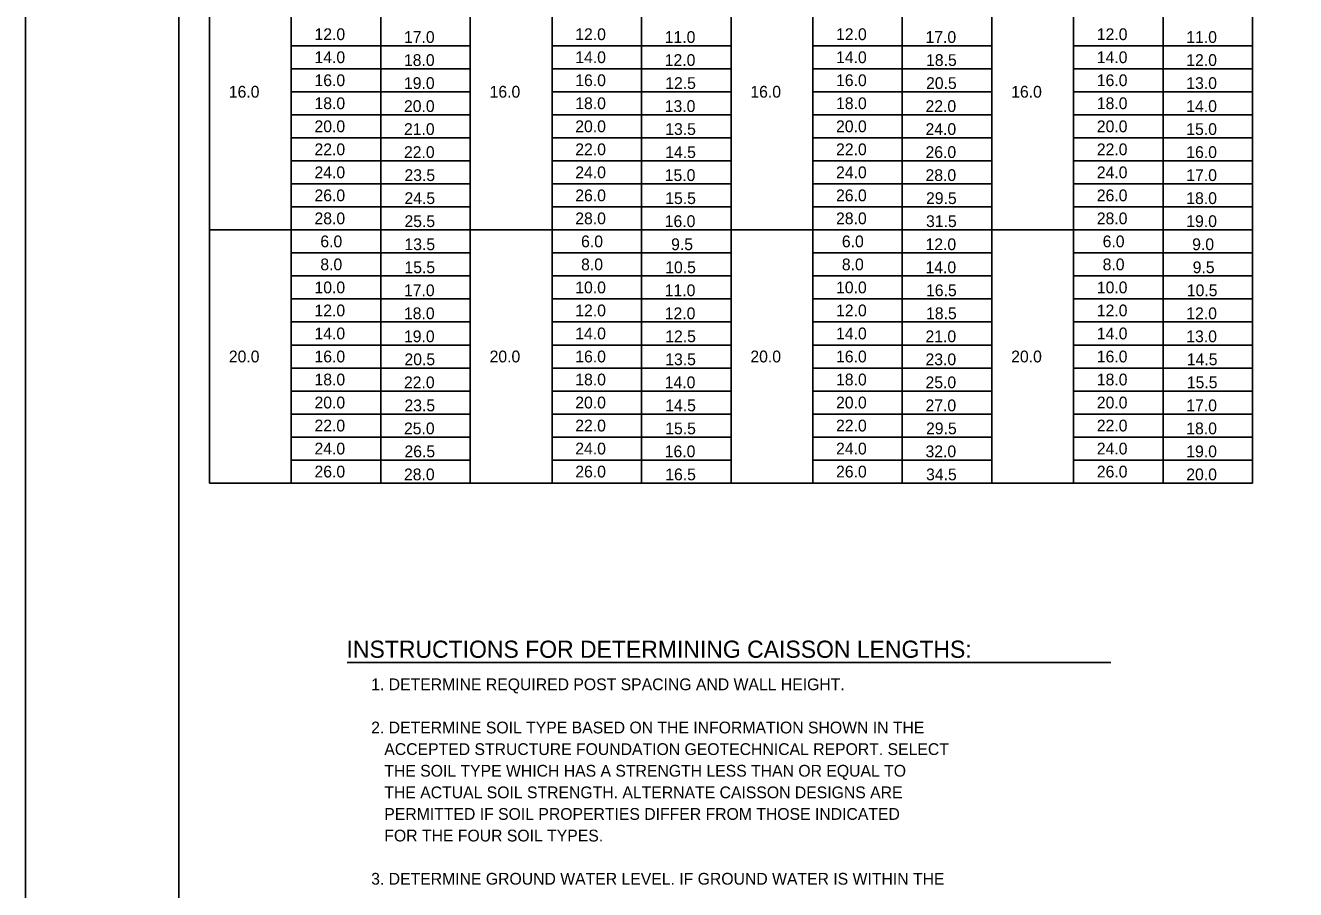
# Model space of a CAD drawing. Extents: x 3475 to 6558, y -3780 to 1166.
# Drawn here: x 3761.3 to 4092.6, y -3449.2 to -3224 of the extents above; entities that cross this region are included whole.
import ezdxf

# ---------------------------------------------------------------- set-up
doc = ezdxf.new("R2010")
doc.units = 0
for name, color, linetype in [('1', 7, 'Continuous'), ('2', 7, 'Continuous'), ('PLT-BNDY', 7, 'Continuous')]:
    doc.layers.add(name, color=color, linetype=linetype)

msp = doc.modelspace()

# ---------------------------------------------------------------- linework, layer by layer
at = {"layer": '1'}
for p, q in [((3809.33, -3015.3), (3809.33, -3343.24)), ((4081.34, -3015.3), (4081.34, -3343.24)), ((3877.34, -3055.3), (3877.34, -3343.24)), ((3945.34, -3055.3), (3945.34, -3343.24)), ((4013.34, -3055.3), (4013.34, -3343.24)), ((3830.67, -3343.24), (3830.67, -3110.49)), ((3854, -3110.49), (3854, -3343.24)), ((3898.67, -3343.24), (3898.67, -3110.49)), ((3922, -3110.49), (3922, -3343.24)), ((3966.67, -3343.24), (3966.67, -3110.49)), ((3990, -3110.49), (3990, -3343.24)), ((4034.67, -3343.24), (4034.67, -3110.49)), ((4058, -3110.49), (4058, -3343.24)), ((3830.67, -3229.24), (3877.34, -3229.24)), ((3898.67, -3229.24), (3945.34, -3229.24)), ((3966.67, -3229.24), (4013.34, -3229.24)), ((4034.67, -3229.24), (4081.34, -3229.24)), ((3830.67, -3235.24), (3877.34, -3235.24)), ((3898.67, -3235.24), (3945.34, -3235.24)), ((3966.67, -3235.24), (4013.34, -3235.24)), ((4034.67, -3235.24), (4081.34, -3235.24)), ((3830.67, -3241.24), (3877.34, -3241.24)), ((3898.67, -3241.24), (3945.34, -3241.24)), ((3966.67, -3241.24), (4013.34, -3241.24)), ((4034.67, -3241.24), (4081.34, -3241.24)), ((3830.67, -3247.24), (3877.34, -3247.24)), ((3898.67, -3247.24), (3945.34, -3247.24)), ((3966.67, -3247.24), (4013.34, -3247.24)), ((4034.67, -3247.24), (4081.34, -3247.24)), ((3830.67, -3253.24), (3877.34, -3253.24)), ((3898.67, -3253.24), (3945.34, -3253.24)), ((3966.67, -3253.24), (4013.34, -3253.24)), ((4034.67, -3253.24), (4081.34, -3253.24)), ((3830.67, -3259.24), (3877.34, -3259.24)), ((3898.67, -3259.24), (3945.34, -3259.24)), ((3966.67, -3259.24), (4013.34, -3259.24)), ((4034.67, -3259.24), (4081.34, -3259.24)), ((3830.67, -3265.24), (3877.34, -3265.24)), ((3898.67, -3265.24), (3945.34, -3265.24)), ((3966.67, -3265.24), (4013.34, -3265.24)), ((4034.67, -3265.24), (4081.34, -3265.24)), ((3830.67, -3271.24), (3877.34, -3271.24)), ((3898.67, -3271.24), (3945.34, -3271.24)), ((3966.67, -3271.24), (4013.34, -3271.24)), ((4034.67, -3271.24), (4081.34, -3271.24)), ((3809.33, -3277.25), (4081.34, -3277.25)), ((3865.67, -3281), (3865.67, -3281)), ((3933.67, -3281), (3933.67, -3281)), ((4001.67, -3281), (4001.67, -3281)), ((4069.67, -3281), (4069.67, -3281)), ((3830.67, -3283.25), (3877.34, -3283.25)), ((3830.67, -3283.25), (3877.34, -3283.25)), ((3898.67, -3283.25), (3945.34, -3283.25)), ((3966.67, -3283.25), (4013.34, -3283.25)), ((4034.67, -3283.25), (4081.34, -3283.25)), ((3830.67, -3289.25), (3877.34, -3289.25)), ((3898.67, -3289.25), (3945.34, -3289.25)), ((3966.67, -3289.25), (4013.34, -3289.25)), ((4034.67, -3289.25), (4081.34, -3289.25)), ((3830.67, -3295.25), (3877.34, -3295.25)), ((3898.67, -3295.25), (3945.34, -3295.25)), ((3966.67, -3295.25), (4013.34, -3295.25)), ((4034.67, -3295.25), (4081.34, -3295.25)), ((3830.67, -3301.25), (3877.34, -3301.25)), ((3898.67, -3301.25), (3945.34, -3301.25)), ((3966.67, -3301.25), (4013.34, -3301.25)), ((4034.67, -3301.25), (4081.34, -3301.25)), ((3830.67, -3307.25), (3877.34, -3307.25)), ((3898.67, -3307.25), (3945.34, -3307.25)), ((3966.67, -3307.25), (4013.34, -3307.25)), ((4034.67, -3307.25), (4081.34, -3307.25)), ((3830.67, -3313.25), (3877.34, -3313.25)), ((3898.67, -3313.25), (3945.34, -3313.25)), ((3966.67, -3313.25), (4013.34, -3313.25)), ((4034.67, -3313.25), (4081.34, -3313.25)), ((3830.67, -3319.25), (3877.34, -3319.25)), ((3898.67, -3319.25), (3945.34, -3319.25)), ((3966.67, -3319.25), (4013.34, -3319.25)), ((4034.67, -3319.25), (4081.34, -3319.25)), ((3830.67, -3325.25), (3877.34, -3325.25)), ((3898.67, -3325.25), (3945.34, -3325.25)), ((3966.67, -3325.25), (4013.34, -3325.25)), ((4034.67, -3325.25), (4081.34, -3325.25)), ((3830.67, -3331.25), (3877.34, -3331.25)), ((3898.67, -3331.25), (3945.34, -3331.25)), ((3966.67, -3331.25), (4013.34, -3331.25)), ((4034.67, -3331.25), (4081.34, -3331.25)), ((3830.67, -3337.25), (3877.34, -3337.25)), ((3898.67, -3337.25), (3945.34, -3337.25)), ((3966.67, -3337.25), (4013.34, -3337.25)), ((4034.67, -3337.25), (4081.34, -3337.25)), ((3809.33, -3343.24), (4081.34, -3343.24)), ((3845.27, -3390), (4044.35, -3390))]:
    msp.add_line(p, q, dxfattribs=at)
at = {"layer": '2'}
msp.add_line((3801.34, -3571.31), (3801.34, -3007.31), dxfattribs=at)
at = {"layer": 'PLT-BNDY'}
msp.add_lwpolyline([(3761.34, -2992.31), (4602.34, -2992.31), (4602.34, -3586.31), (3761.34, -3586.31)], close=True, dxfattribs=at)

# ---------------------------------------------------------------- texts
at = {"layer": '1'}
for s, height, p in [('12.0', 3.07, (3836.73, -3227.78)), ('17.0', 3.07, (3860.06, -3228.52)), ('12.0', 3.07, (3904.73, -3227.78)), ('11.0', 3.07, (3928.06, -3228.52)), ('12.0', 3.07, (3972.73, -3227.78)), ('17.0', 3.07, (3996.06, -3228.52)), ('12.0', 3.07, (4040.73, -3227.78)), ('11.0', 3.07, (4064.06, -3228.52)), ('14.0', 3.07, (3836.73, -3233.78)), ('18.0', 3.07, (3860.06, -3234.52)), ('14.0', 3.07, (3904.73, -3233.78)), ('12.0', 3.07, (3928.06, -3234.52)), ('14.0', 3.07, (3972.73, -3233.78)), ('18.5', 3.07, (3996.2, -3234.52)), ('14.0', 3.07, (4040.73, -3233.78)), ('12.0', 3.07, (4064.06, -3234.52)), ('16.0', 3.07, (3836.73, -3239.78)), ('19.0', 3.07, (3860.06, -3240.52)), ('16.0', 3.07, (3904.73, -3239.78)), ('12.5', 3.07, (3928.19, -3240.52)), ('16.0', 3.07, (3972.73, -3239.78)), ('20.5', 3.07, (3996.2, -3240.52)), ('16.0', 3.07, (4040.73, -3239.78)), ('13.0', 3.07, (4064.06, -3240.52)), ('16.0', 3.07, (3814.39, -3242.78)), ('16.0', 3.07, (3882.39, -3242.78)), ('16.0', 3.07, (3950.39, -3242.78)), ('16.0', 3.07, (4018.4, -3242.78)), ('18.0', 3.07, (3836.73, -3245.78)), ('20.0', 3.07, (3860.06, -3246.52)), ('18.0', 3.07, (3904.73, -3245.78)), ('13.0', 3.07, (3928.06, -3246.52)), ('18.0', 3.07, (3972.73, -3245.78)), ('22.0', 3.07, (3996.06, -3246.52)), ('18.0', 3.07, (4040.73, -3245.78)), ('14.0', 3.07, (4064.06, -3246.52)), ('20.0', 3.07, (3836.73, -3251.78)), ('20.0', 3.07, (3904.73, -3251.78)), ('20.0', 3.07, (3972.73, -3251.78)), ('20.0', 3.07, (4040.73, -3251.78)), ('21.0', 3.07, (3860.06, -3252.51)), ('13.5', 3.07, (3928.19, -3252.51)), ('24.0', 3.07, (3996.06, -3252.51)), ('15.0', 3.07, (4064.06, -3252.51)), ('22.0', 3.07, (3836.73, -3257.78)), ('22.0', 3.07, (3860.06, -3258.51)), ('22.0', 3.07, (3904.73, -3257.78)), ('14.5', 3.07, (3928.19, -3258.51)), ('22.0', 3.07, (3972.73, -3257.78)), ('26.0', 3.07, (3996.06, -3258.51)), ('22.0', 3.07, (4040.73, -3257.78)), ('16.0', 3.07, (4064.06, -3258.51)), ('24.0', 3.07, (3836.73, -3263.78)), ('23.5', 3.07, (3860.19, -3264.51)), ('24.0', 3.07, (3904.73, -3263.78)), ('15.0', 3.07, (3928.06, -3264.51)), ('24.0', 3.07, (3972.73, -3263.78)), ('28.0', 3.07, (3996.06, -3264.51)), ('24.0', 3.07, (4040.73, -3263.78)), ('17.0', 3.07, (4064.06, -3264.51)), ('26.0', 3.07, (3836.73, -3269.78)), ('24.5', 3.07, (3860.19, -3270.51)), ('26.0', 3.07, (3904.73, -3269.78)), ('15.5', 3.07, (3928.19, -3270.51)), ('26.0', 3.07, (3972.73, -3269.78)), ('29.5', 3.07, (3996.2, -3270.51)), ('26.0', 3.07, (4040.73, -3269.78)), ('18.0', 3.07, (4064.06, -3270.51)), ('28.0', 3.07, (3836.73, -3275.78)), ('25.5', 3.07, (3860.19, -3276.51)), ('28.0', 3.07, (3904.73, -3275.78)), ('16.0', 3.07, (3928.06, -3276.51)), ('28.0', 3.07, (3972.73, -3275.78)), ('31.5', 3.07, (3996.2, -3276.51)), ('28.0', 3.07, (4040.73, -3275.78)), ('19.0', 3.07, (4064.06, -3276.51)), ('6.0', 3.07, (3838.25, -3281.78)), ('6.0', 3.07, (3906.25, -3281.78)), ('6.0', 3.07, (3974.25, -3281.78)), ('6.0', 3.07, (4042.25, -3281.78)), ('13.5', 3.07, (3860.19, -3282.53)), ('9.5', 3.07, (3929.73, -3282.53)), ('12.0', 3.07, (3996.06, -3282.53)), ('9.0', 3.07, (4065.6, -3282.53)), ('8.0', 3.07, (3838.25, -3287.78)), ('15.5', 3.07, (3860.19, -3288.53)), ('8.0', 3.07, (3906.25, -3287.78)), ('10.5', 3.07, (3928.19, -3288.53)), ('8.0', 3.07, (3974.25, -3287.78)), ('14.0', 3.07, (3996.06, -3288.53)), ('8.0', 3.07, (4042.25, -3287.78)), ('9.5', 3.07, (4065.73, -3288.53)), ('10.0', 3.07, (3836.73, -3293.78)), ('17.0', 3.07, (3860.06, -3294.53)), ('10.0', 3.07, (3904.73, -3293.78)), ('11.0', 3.07, (3928.06, -3294.53)), ('10.0', 3.07, (3972.73, -3293.78)), ('16.5', 3.07, (3996.2, -3294.53)), ('10.0', 3.07, (4040.73, -3293.78)), ('10.5', 3.07, (4064.2, -3294.53)), ('12.0', 3.07, (3836.73, -3299.78)), ('18.0', 3.07, (3860.06, -3300.53)), ('12.0', 3.07, (3904.73, -3299.78)), ('12.0', 3.07, (3928.06, -3300.53)), ('12.0', 3.07, (3972.73, -3299.78)), ('18.5', 3.07, (3996.2, -3300.53)), ('12.0', 3.07, (4040.73, -3299.78)), ('12.0', 3.07, (4064.06, -3300.53)), ('14.0', 3.07, (3836.73, -3305.78)), ('19.0', 3.07, (3860.06, -3306.52)), ('14.0', 3.07, (3904.73, -3305.78)), ('12.5', 3.07, (3928.19, -3306.52)), ('14.0', 3.07, (3972.73, -3305.78)), ('21.0', 3.07, (3996.06, -3306.52)), ('14.0', 3.07, (4040.73, -3305.78)), ('13.0', 3.07, (4064.06, -3306.52)), ('20.0', 3.07, (3814.39, -3311.78)), ('16.0', 3.07, (3836.73, -3311.78)), ('20.0', 3.07, (3882.39, -3311.78)), ('16.0', 3.07, (3904.73, -3311.78)), ('20.0', 3.07, (3950.39, -3311.78)), ('16.0', 3.07, (3972.73, -3311.78)), ('20.0', 3.07, (4018.4, -3311.78)), ('16.0', 3.07, (4040.73, -3311.78)), ('20.5', 3.07, (3860.19, -3312.52)), ('13.5', 3.07, (3928.19, -3312.52)), ('23.0', 3.07, (3996.06, -3312.52)), ('14.5', 3.07, (4064.2, -3312.52)), ('18.0', 3.07, (3836.73, -3317.78)), ('22.0', 3.07, (3860.06, -3318.52)), ('18.0', 3.07, (3904.73, -3317.78)), ('14.0', 3.07, (3928.06, -3318.52)), ('18.0', 3.07, (3972.73, -3317.78)), ('25.0', 3.07, (3996.06, -3318.52)), ('18.0', 3.07, (4040.73, -3317.78)), ('15.5', 3.07, (4064.2, -3318.52)), ('20.0', 3.07, (3836.73, -3323.78)), ('23.5', 3.07, (3860.19, -3324.52)), ('20.0', 3.07, (3904.73, -3323.78)), ('14.5', 3.07, (3928.19, -3324.52)), ('20.0', 3.07, (3972.73, -3323.78)), ('27.0', 3.07, (3996.06, -3324.52)), ('20.0', 3.07, (4040.73, -3323.78)), ('17.0', 3.07, (4064.06, -3324.52)), ('22.0', 3.07, (3836.73, -3329.78)), ('25.0', 3.07, (3860.06, -3330.52)), ('22.0', 3.07, (3904.73, -3329.78)), ('15.5', 3.07, (3928.19, -3330.52)), ('22.0', 3.07, (3972.73, -3329.78)), ('29.5', 3.07, (3996.2, -3330.52)), ('22.0', 3.07, (4040.73, -3329.78)), ('18.0', 3.07, (4064.06, -3330.52)), ('24.0', 3.07, (3836.73, -3335.78)), ('26.5', 3.07, (3860.19, -3336.51)), ('24.0', 3.07, (3904.73, -3335.78)), ('16.0', 3.07, (3928.06, -3336.51)), ('24.0', 3.07, (3972.73, -3335.78)), ('32.0', 3.07, (3996.06, -3336.51)), ('24.0', 3.07, (4040.73, -3335.78)), ('19.0', 3.07, (4064.06, -3336.51)), ('26.0', 3.07, (3836.73, -3341.78)), ('26.0', 3.07, (3904.73, -3341.78)), ('26.0', 3.07, (3972.73, -3341.78)), ('26.0', 3.07, (4040.73, -3341.78)), ('28.0', 3.07, (3860.06, -3342.51)), ('16.5', 3.07, (3928.19, -3342.51)), ('34.5', 3.07, (3996.2, -3342.51)), ('20.0', 3.07, (4064.06, -3342.51)), ('INSTRUCTIONS FOR DETERMINING CAISSON LENGTHS:', 4.4775, (3845.09, -3388.78)), ('1. DETERMINE REQUIRED POST SPACING AND WALL HEIGHT.', 3.072, (3851.51, -3397.23)), ('2. DETERMINE SOIL TYPE BASED ON THE INFORMATION SHOWN IN THE', 3.072, (3851.51, -3408.49)), ('   ACCEPTED STRUCTURE FOUNDATION GEOTECHNICAL REPORT. SELECT', 3.072, (3851.51, -3414.12)), ('   THE SOIL TYPE WHICH HAS A STRENGTH LESS THAN OR EQUAL TO', 3.072, (3851.51, -3419.76)), ('   THE ACTUAL SOIL STRENGTH. ALTERNATE CAISSON DESIGNS ARE', 3.072, (3851.51, -3425.39)), ('   PERMITTED IF SOIL PROPERTIES DIFFER FROM THOSE INDICATED', 3.072, (3851.51, -3431.02)), ('   FOR THE FOUR SOIL TYPES.', 3.072, (3851.51, -3436.65)), ('3. DETERMINE GROUND WATER LEVEL. IF GROUND WATER IS WITHIN THE', 3.072, (3851.51, -3447.91))]:
    msp.add_text(s, height=height, dxfattribs=at).set_placement(p)

doc.saveas('drawing.dxf')
